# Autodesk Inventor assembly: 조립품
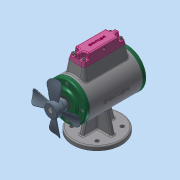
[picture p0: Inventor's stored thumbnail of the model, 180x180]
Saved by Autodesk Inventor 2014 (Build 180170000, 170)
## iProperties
Created: 2023-01
Part Number: 조립품
Document SubType Name: Assembly
Designer: dg
Author: dg
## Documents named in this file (19)
- C:\Users\dg\Downloads\630106V1020\조립품.iam
- C:\Users\dg\Downloads\630106V1020\본체.ipt
- C:\Users\dg\Downloads\630106V1020\가변스프링.ipt
- C:\Users\dg\Downloads\630106V1020\뒤커버.ipt
- C:\Users\dg\Downloads\630106V1020\멈춤나사 M4 x 8.ipt
- C:\Users\dg\Downloads\630106V1020\베어링 6203.ipt
- C:\Users\dg\Downloads\630106V1020\볼트 M4 x 12.ipt
- C:\Users\dg\Downloads\630106V1020\볼트 M4 x 16.ipt
- C:\Users\dg\Downloads\630106V1020\부시.ipt
- C:\Users\dg\Downloads\630106V1020\슬라이드.ipt
- C:\Users\dg\Downloads\630106V1020\앞커버.ipt
- C:\Users\dg\Downloads\630106V1020\오일실 17 30 8.ipt
- C:\Users\dg\Downloads\630106V1020\축.ipt
- C:\Users\dg\Downloads\630106V1020\키 5 x 5 x 18.ipt
- C:\Users\dg\Downloads\630106V1020\팬날개.ipt
- 팬날개.ipt
- C:\Users\dg\Downloads\630106V1020\헤더커버.ipt
- C:\Users\dg\Downloads\630106V1020\가변스프링2.ipt
- C:\Users\dg\Downloads\630106V1020\가변스프링3.ipt
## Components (4 placed, 4 different names)
1. 가변스프링:1
2. 가변스프링2:1
3. 가변스프링3:1
4. 헤더커버:1
